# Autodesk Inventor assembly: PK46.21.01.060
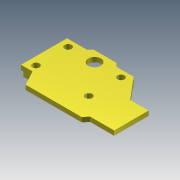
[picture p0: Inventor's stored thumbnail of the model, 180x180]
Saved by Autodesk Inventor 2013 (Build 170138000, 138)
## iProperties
Created: 2005-04
Part Number: PK46.21.01.060
Document SubType Name: Assembly
Designer: salex
Manufacturer: Standard
Standards Organization: Custom
Author: salex
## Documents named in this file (3)
- C:\Product Design Suite 2013\Data\Assy, Chassis, Front\PK46.21.01.060.iam
- C:\Product Design Suite 2013\Data\Assy, Chassis, Front\PK46.21.01.017.ipt
- C:\Product Design Suite 2013\Data\Assy, Chassis, Front\PK46.21.01.018.ipt
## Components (3 placed, 2 different names)
1. PK46.21.01.017:1 — Insert:1, Mate:1, Insert:2, Mate:2
2. PK46.21.01.018:1 — Insert:2, Mate:2
3. PK46.21.01.018:2 — Insert:1, Mate:1
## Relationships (4: Insert 2, Mate 2)
- Insert:1: PK46.21.01.017:1 ↔ PK46.21.01.018:2
- Mate:1: PK46.21.01.017:1 ↔ PK46.21.01.018:2
- Insert:2: PK46.21.01.017:1 ↔ PK46.21.01.018:1
- Mate:2: PK46.21.01.017:1 ↔ PK46.21.01.018:1
